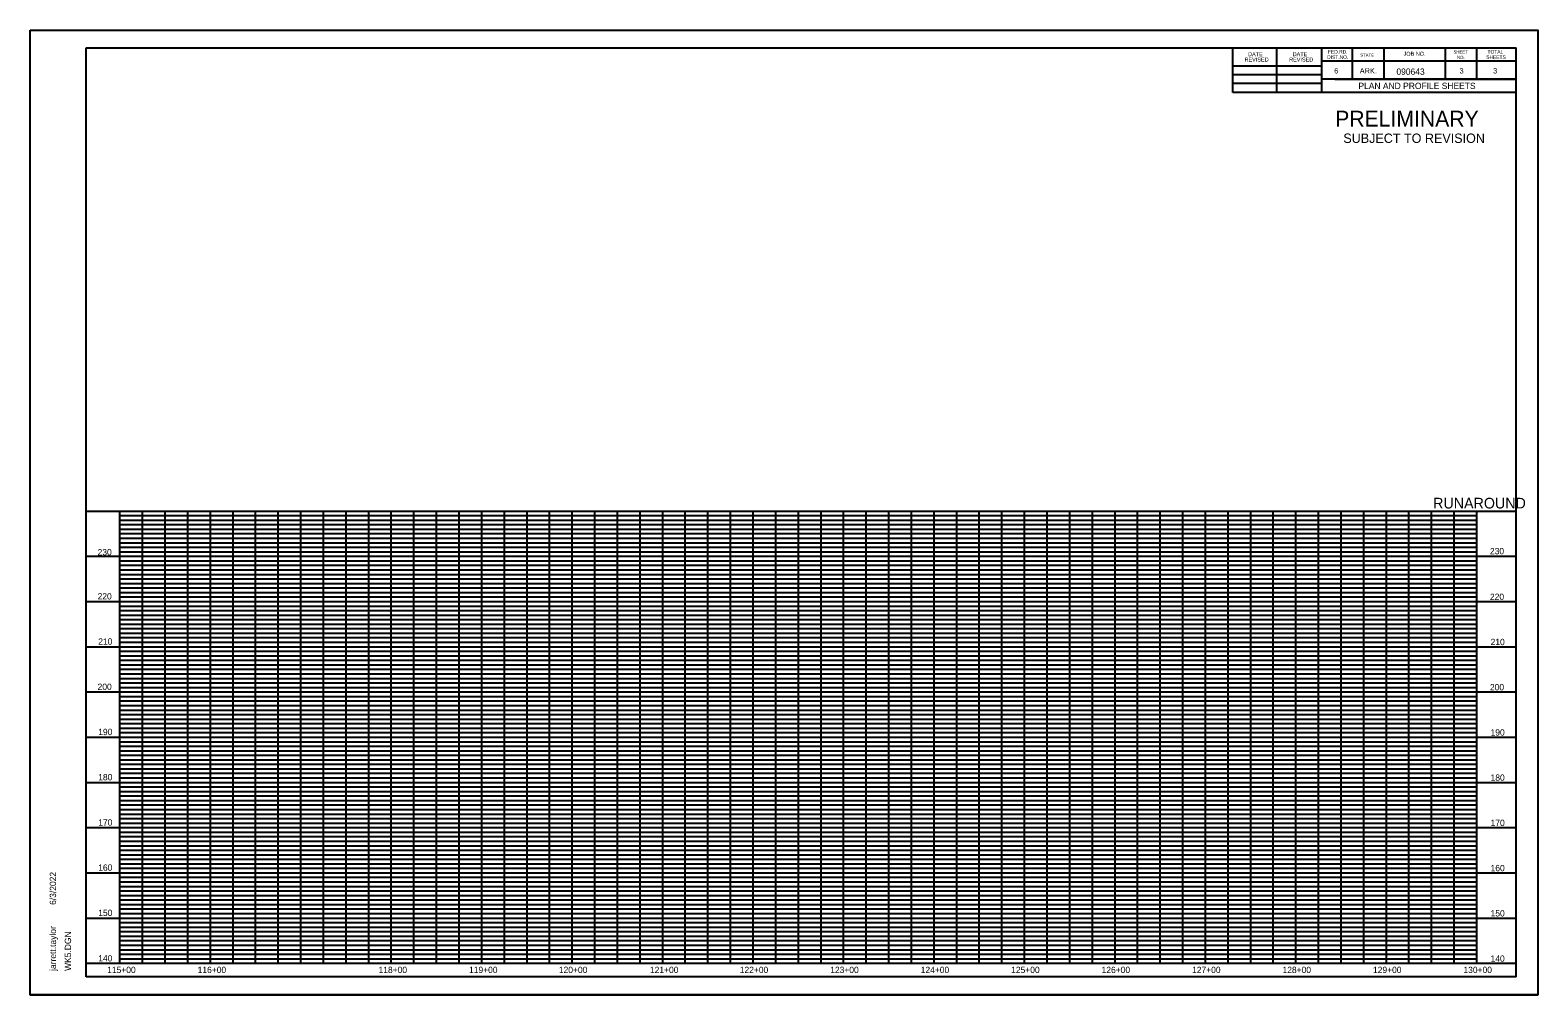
# Model space of a CAD drawing. Extents: x 1384905 to 1388477, y 1972734 to 1975234.
# Drawn here: x 1386810 to 1388477, y 1972777 to 1973844 of the extents above; entities that cross this region are included whole.
import ezdxf

# ---------------------------------------------------------------- set-up
doc = ezdxf.new("R2010")
doc.units = 0
for name, color, linetype in [('Default', 7, 'Continuous'), ('R_Border', 7, 'Continuous'), ('R_Border Prem', 7, 'Continuous'), ('R_Grid', 7, 'Continuous'), ('R_No Plot', 7, 'Continuous')]:
    doc.layers.add(name, color=color, linetype=linetype)

msp = doc.modelspace()

# ---------------------------------------------------------------- linework, layer by layer
at = {"layer": 'R_Border'}
for p, q in [((1386872.4, 1973824.6), (1388453.3, 1973824.6)), ((1386872.4, 1972797.3), (1386872.4, 1973824.6)), ((1387954.6, 1973823.3), (1387954.6, 1973823.3)), ((1387954.6, 1973823.3), (1387954.6, 1973823.3)), ((1388140.1, 1973775.2), (1388140.1, 1973824.6)), ((1388188.5, 1973775.2), (1388188.5, 1973824.6)), ((1388237.8, 1973824.6), (1388237.8, 1973775.2)), ((1388272, 1973824.6), (1388272, 1973789.9)), ((1388306.7, 1973824.6), (1388306.7, 1973789.9)), ((1388374.6, 1973824.6), (1388374.6, 1973789.9)), ((1388409.3, 1973824.6), (1388409.3, 1973789.9)), ((1388453.3, 1972797.3), (1388453.3, 1973824.6)), ((1388453.3, 1973809.9), (1388237.8, 1973809.9)), ((1388140.1, 1973804.5), (1388237.8, 1973804.5)), ((1388140.1, 1973795.2), (1388237.8, 1973795.2)), ((1388453.3, 1973789.9), (1388237.8, 1973789.9)), ((1388252.6, 1973789.9), (1388453.3, 1973789.9)), ((1388140.1, 1973785.5), (1388237.8, 1973785.5)), ((1388453.3, 1973775.2), (1388140.1, 1973775.2)), ((1388453.3, 1973312), (1386872.4, 1973312)), ((1386909.7, 1972812), (1386909.7, 1973312)), ((1386959.7, 1972812), (1386959.7, 1973312)), ((1387009.7, 1972812), (1387009.7, 1973312)), ((1387059.7, 1972812), (1387059.7, 1973312)), ((1387109.7, 1972812), (1387109.7, 1973312)), ((1387159.7, 1972812), (1387159.7, 1973312)), ((1387209.7, 1972812), (1387209.7, 1973312)), ((1387259.7, 1972812), (1387259.7, 1973312)), ((1387309.7, 1972812), (1387309.7, 1973312)), ((1387359.7, 1972812), (1387359.7, 1973312)), ((1387409.7, 1972812), (1387409.7, 1973312)), ((1387459.7, 1972812), (1387459.7, 1973312)), ((1387509.7, 1972812), (1387509.7, 1973312)), ((1387559.7, 1972812), (1387559.7, 1973312)), ((1387609.7, 1972812), (1387609.7, 1973312)), ((1387659.7, 1972812), (1387659.7, 1973312)), ((1387709.7, 1972812), (1387709.7, 1973312)), ((1387759.7, 1972812), (1387759.7, 1973312)), ((1387809.7, 1972812), (1387809.7, 1973312)), ((1387859.7, 1972812), (1387859.7, 1973312)), ((1387909.7, 1972812), (1387909.7, 1973312)), ((1387959.7, 1972812), (1387959.7, 1973312)), ((1388009.7, 1972812), (1388009.7, 1973312)), ((1388059.7, 1972812), (1388059.7, 1973312)), ((1388109.7, 1972812), (1388109.7, 1973312)), ((1388159.7, 1972812), (1388159.7, 1973312)), ((1388209.7, 1972812), (1388209.7, 1973312)), ((1388259.7, 1972812), (1388259.7, 1973312)), ((1388309.7, 1972812), (1388309.7, 1973312)), ((1388359.7, 1972812), (1388359.7, 1973312)), ((1388409.7, 1972812), (1388409.7, 1973312)), ((1388453.3, 1973262), (1386872.4, 1973262)), ((1388453.3, 1973212), (1386872.4, 1973212)), ((1388453.3, 1973162), (1386872.4, 1973162)), ((1388453.3, 1973112), (1386872.4, 1973112)), ((1388453.3, 1973062), (1386872.4, 1973062)), ((1388453.3, 1973012), (1386872.4, 1973012)), ((1388453.3, 1972962), (1386872.4, 1972962)), ((1388453.3, 1972912), (1386872.4, 1972912)), ((1388453.3, 1972862), (1386872.4, 1972862)), ((1388453.3, 1972812), (1386872.4, 1972812)), ((1386872.4, 1972797.3), (1386872.4, 1972797.3)), ((1388453.3, 1972797.3), (1386872.4, 1972797.3))]:
    msp.add_line(p, q, dxfattribs=at)
at = {"layer": 'R_Grid'}
for p, q in [((1388409.7, 1973307), (1386909.7, 1973307)), ((1386934.7, 1972812), (1386934.7, 1973312)), ((1386984.7, 1972812), (1386984.7, 1973312)), ((1387034.7, 1972812), (1387034.7, 1973312)), ((1387084.7, 1972812), (1387084.7, 1973312)), ((1387134.7, 1972812), (1387134.7, 1973312)), ((1387184.7, 1972812), (1387184.7, 1973312)), ((1387234.7, 1972812), (1387234.7, 1973312)), ((1387284.7, 1972812), (1387284.7, 1973312)), ((1387334.7, 1972812), (1387334.7, 1973312)), ((1387384.7, 1972812), (1387384.7, 1973312)), ((1387434.7, 1972812), (1387434.7, 1973312)), ((1387484.7, 1972812), (1387484.7, 1973312)), ((1387534.7, 1972812), (1387534.7, 1973312)), ((1387584.7, 1972812), (1387584.7, 1973312)), ((1387634.7, 1972812), (1387634.7, 1973312)), ((1387684.7, 1972812), (1387684.7, 1973312)), ((1387734.7, 1972812), (1387734.7, 1973312)), ((1387784.7, 1972812), (1387784.7, 1973312)), ((1387834.7, 1972812), (1387834.7, 1973312)), ((1387884.7, 1972812), (1387884.7, 1973312)), ((1387934.7, 1972812), (1387934.7, 1973312)), ((1387984.7, 1972812), (1387984.7, 1973312)), ((1388034.7, 1972812), (1388034.7, 1973312)), ((1388084.7, 1972812), (1388084.7, 1973312)), ((1388134.7, 1972812), (1388134.7, 1973312)), ((1388184.7, 1972812), (1388184.7, 1973312)), ((1388234.7, 1972812), (1388234.7, 1973312)), ((1388284.7, 1972812), (1388284.7, 1973312)), ((1388334.7, 1972812), (1388334.7, 1973312)), ((1388384.7, 1972812), (1388384.7, 1973312)), ((1388409.7, 1973302), (1386909.7, 1973302)), ((1388409.7, 1973297), (1386909.7, 1973297)), ((1388409.7, 1973292), (1386909.7, 1973292)), ((1388409.7, 1973287), (1386909.7, 1973287)), ((1388409.7, 1973282), (1386909.7, 1973282)), ((1388409.7, 1973277), (1386909.7, 1973277)), ((1388409.7, 1973272), (1386909.7, 1973272)), ((1388409.7, 1973267), (1386909.7, 1973267)), ((1388409.7, 1973257), (1386909.7, 1973257)), ((1388409.7, 1973252), (1386909.7, 1973252)), ((1388409.7, 1973247), (1386909.7, 1973247)), ((1388409.7, 1973242), (1386909.7, 1973242)), ((1388409.7, 1973237), (1386909.7, 1973237)), ((1388409.7, 1973232), (1386909.7, 1973232)), ((1388409.7, 1973227), (1386909.7, 1973227)), ((1388409.7, 1973222), (1386909.7, 1973222)), ((1388409.7, 1973217), (1386909.7, 1973217)), ((1388409.7, 1973207), (1386909.7, 1973207)), ((1388409.7, 1973202), (1386909.7, 1973202)), ((1388409.7, 1973197), (1386909.7, 1973197)), ((1388409.7, 1973192), (1386909.7, 1973192)), ((1388409.7, 1973187), (1386909.7, 1973187)), ((1388409.7, 1973182), (1386909.7, 1973182)), ((1388409.7, 1973177), (1386909.7, 1973177)), ((1388409.7, 1973172), (1386909.7, 1973172)), ((1388409.7, 1973167), (1386909.7, 1973167)), ((1388409.7, 1973157), (1386909.7, 1973157)), ((1388409.7, 1973152), (1386909.7, 1973152)), ((1388409.7, 1973147), (1386909.7, 1973147)), ((1388409.7, 1973142), (1386909.7, 1973142)), ((1388409.7, 1973137), (1386909.7, 1973137)), ((1388409.7, 1973132), (1386909.7, 1973132)), ((1388409.7, 1973127), (1386909.7, 1973127)), ((1388409.7, 1973122), (1386909.7, 1973122)), ((1388409.7, 1973117), (1386909.7, 1973117)), ((1388409.7, 1973107), (1386909.7, 1973107)), ((1388409.7, 1973102), (1386909.7, 1973102)), ((1388409.7, 1973097), (1386909.7, 1973097)), ((1388409.7, 1973092), (1386909.7, 1973092)), ((1388409.7, 1973087), (1386909.7, 1973087)), ((1388409.7, 1973082), (1386909.7, 1973082)), ((1388409.7, 1973077), (1386909.7, 1973077)), ((1388409.7, 1973072), (1386909.7, 1973072)), ((1388409.7, 1973067), (1386909.7, 1973067)), ((1388409.7, 1973057), (1386909.7, 1973057)), ((1388409.7, 1973052), (1386909.7, 1973052)), ((1388409.7, 1973047), (1386909.7, 1973047)), ((1388409.7, 1973042), (1386909.7, 1973042)), ((1388409.7, 1973037), (1386909.7, 1973037)), ((1388409.7, 1973032), (1386909.7, 1973032)), ((1388409.7, 1973027), (1386909.7, 1973027)), ((1388409.7, 1973022), (1386909.7, 1973022)), ((1388409.7, 1973017), (1386909.7, 1973017)), ((1388409.7, 1973007), (1386909.7, 1973007)), ((1388409.7, 1973002), (1386909.7, 1973002)), ((1388409.7, 1972997), (1386909.7, 1972997)), ((1388409.7, 1972992), (1386909.7, 1972992)), ((1388409.7, 1972987), (1386909.7, 1972987)), ((1388409.7, 1972982), (1386909.7, 1972982)), ((1388409.7, 1972977), (1386909.7, 1972977)), ((1388409.7, 1972972), (1386909.7, 1972972)), ((1388409.7, 1972967), (1386909.7, 1972967)), ((1388409.7, 1972957), (1386909.7, 1972957)), ((1388409.7, 1972952), (1386909.7, 1972952)), ((1388409.7, 1972947), (1386909.7, 1972947)), ((1388409.7, 1972942), (1386909.7, 1972942)), ((1388409.7, 1972937), (1386909.7, 1972937)), ((1388409.7, 1972932), (1386909.7, 1972932)), ((1388409.7, 1972927), (1386909.7, 1972927)), ((1388409.7, 1972922), (1386909.7, 1972922)), ((1388409.7, 1972917), (1386909.7, 1972917)), ((1388409.7, 1972907), (1386909.7, 1972907)), ((1388409.7, 1972902), (1386909.7, 1972902)), ((1388409.7, 1972897), (1386909.7, 1972897)), ((1388409.7, 1972892), (1386909.7, 1972892)), ((1388409.7, 1972887), (1386909.7, 1972887)), ((1388409.7, 1972882), (1386909.7, 1972882)), ((1388409.7, 1972877), (1386909.7, 1972877)), ((1388409.7, 1972872), (1386909.7, 1972872)), ((1388409.7, 1972867), (1386909.7, 1972867)), ((1388409.7, 1972857), (1386909.7, 1972857)), ((1388409.7, 1972852), (1386909.7, 1972852)), ((1388409.7, 1972847), (1386909.7, 1972847)), ((1388409.7, 1972842), (1386909.7, 1972842)), ((1388409.7, 1972837), (1386909.7, 1972837)), ((1388409.7, 1972832), (1386909.7, 1972832)), ((1388409.7, 1972827), (1386909.7, 1972827)), ((1388409.7, 1972822), (1386909.7, 1972822)), ((1388409.7, 1972817), (1386909.7, 1972817))]:
    msp.add_line(p, q, dxfattribs=at)
at = {"layer": 'R_No Plot'}
for p, q in [((1386810.5, 1973844.1), (1388477.1, 1973844.1)), ((1386810.4, 1972777.4), (1388477.1, 1972777.4))]:
    msp.add_line(p, q, dxfattribs=at)
msp.add_lwpolyline([(1386810.4, 1973844.1), (1388477.1, 1973844.1), (1388477.1, 1972777.4), (1386810.4, 1972777.4)], close=True, dxfattribs=at)

# ---------------------------------------------------------------- texts
at = {"layer": 'Default'}
for s, p in [('230', (1386885, 1973263.4)), ('230', (1388424.2, 1973264.6)), ('220', (1386885, 1973214.6)), ('220', (1388424.2, 1973214.1)), ('210', (1386885.7, 1973164.6)), ('210', (1388424.9, 1973164.1)), ('200', (1386885, 1973114.6)), ('200', (1388424.2, 1973114.1)), ('190', (1386885.7, 1973064.6)), ('190', (1388424.9, 1973064.1)), ('180', (1386885.7, 1973014.6)), ('180', (1388424.9, 1973014.1)), ('170', (1386885.7, 1972964.6)), ('170', (1388424.9, 1972964.1)), ('160', (1386885.7, 1972914.6)), ('160', (1388424.9, 1972914.1)), ('150', (1386885.7, 1972864.6)), ('150', (1388424.9, 1972864.1)), ('140', (1386885.7, 1972814.3)), ('115+00', (1386895.6, 1972801.5)), ('116+00', (1386995.6, 1972801.5)), ('118+00', (1387195.6, 1972801.5)), ('119+00', (1387295.6, 1972801.5)), ('120+00', (1387394.9, 1972801.5)), ('121+00', (1387495.6, 1972801.5)), ('122+00', (1387594.9, 1972801.5)), ('123+00', (1387694.9, 1972801.5)), ('124+00', (1387794.9, 1972801.5)), ('125+00', (1387894.9, 1972801.5)), ('126+00', (1387994.9, 1972801.5)), ('127+00', (1388094.9, 1972801.5)), ('128+00', (1388194.9, 1972801.5)), ('129+00', (1388294.9, 1972801.5)), ('130+00', (1388394.9, 1972801.5)), ('140', (1388424.9, 1972814))]:
    msp.add_text(s, height=7, dxfattribs=at).set_placement(p)
at = {"layer": 'R_Border'}
for s, height, p in [('REVISED', 4.4, (1388152.9, 1973809.4)), ('DATE', 4.4, (1388156.8, 1973815.3)), ('REVISED', 4.4, (1388202.2, 1973809.4)), ('DATE', 4.4, (1388206.1, 1973815.3)), ('DIST.NO.', 3.91, (1388244.2, 1973812.3)), ('FED.RD.', 3.91, (1388245.2, 1973818.2)), ('STATE', 3.42, (1388280.8, 1973814.8)), ('JOB NO.', 4.4, (1388328.7, 1973815.8)), ('SHEET', 3.42, (1388383.9, 1973818.2)), ('NO.', 3.42, (1388387.8, 1973812.3)), ('SHEETS', 3.91, (1388420.1, 1973812.3)), ('TOTAL', 3.91, (1388421.5, 1973818.2)), ('6', 5.86, (1388252, 1973796.2)), ('ARK.', 5.86, (1388280.3, 1973796.2)), ('090643', 7, (1388320.8, 1973794.7)), ('3', 5.86, (1388390.6, 1973796.2)), ('3', 5.86, (1388427.7, 1973796.2)), ('PLAN AND PROFILE SHEETS', 7, (1388278.8, 1973779)), ('RUNAROUND', 11.79, (1388361.4, 1973315.2))]:
    msp.add_text(s, height=height, dxfattribs=at).set_placement(p)
for s, p in [('6/3/2022', (1386839.1, 1972876.9)), ('jarrett.taylor', (1386839.1, 1972803.9)), ('WK5.DGN', (1386855.7, 1972803.9))]:
    msp.add_text(s, height=7, rotation=90, dxfattribs=at).set_placement(p)
at = {"layer": 'R_Border Prem'}
for s, height, p in [('PRELIMINARY', 17.5, (1388253.1, 1973737.5)), ('SUBJECT TO REVISION', 10.376, (1388262.1, 1973719.4))]:
    msp.add_text(s, height=height, dxfattribs=at).set_placement(p)

doc.saveas('drawing.dxf')
